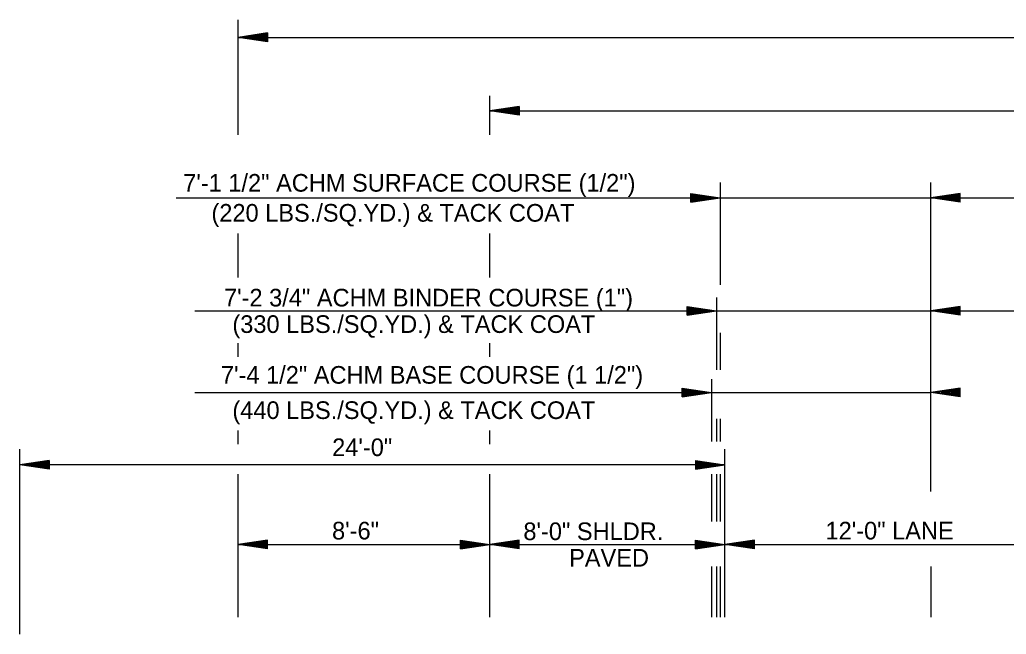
# Model space of a CAD drawing. Extents: x 1371763 to 1372860, y 385599 to 385872.
# Drawn here: x 1372318.58 to 1372352.15, y 385623.49 to 385644.38 of the extents above; entities that cross this region are included whole.
import ezdxf

# ---------------------------------------------------------------- set-up
doc = ezdxf.new("R2010")
doc.units = 0
doc.layers.add('R_Draft', color=7, linetype='Continuous')

msp = doc.modelspace()

# ---------------------------------------------------------------- linework, layer by layer
at = {"layer": 'R_Draft'}
for p, q in [((1372326.012, 385640.475), (1372326.012, 385644.385)), ((1372327.012, 385643.935), (1372326.012, 385643.785)), ((1372326.012, 385643.785), (1372395.148, 385643.785)), ((1372327.012, 385643.635), (1372326.012, 385643.785)), ((1372327.012, 385643.91), (1372326.179, 385643.785)), ((1372327.012, 385643.66), (1372326.179, 385643.785)), ((1372327.012, 385643.884), (1372326.351, 385643.785)), ((1372327.012, 385643.685), (1372326.351, 385643.785)), ((1372327.012, 385643.859), (1372326.517, 385643.785)), ((1372327.012, 385643.71), (1372326.517, 385643.785)), ((1372327.012, 385643.833), (1372326.687, 385643.785)), ((1372327.012, 385643.736), (1372326.687, 385643.785)), ((1372327.012, 385643.808), (1372326.854, 385643.785)), ((1372327.012, 385643.761), (1372326.854, 385643.785)), ((1372327.012, 385643.935), (1372327.012, 385643.635)), ((1372334.576, 385640.475), (1372334.576, 385641.795)), ((1372335.576, 385641.435), (1372334.576, 385641.285)), ((1372335.576, 385641.41), (1372334.743, 385641.285)), ((1372335.576, 385641.384), (1372334.915, 385641.285)), ((1372335.576, 385641.359), (1372335.082, 385641.285)), ((1372335.576, 385641.333), (1372335.251, 385641.285)), ((1372335.576, 385641.435), (1372335.576, 385641.135)), ((1372334.576, 385641.285), (1372386.577, 385641.285)), ((1372335.576, 385641.135), (1372334.576, 385641.285)), ((1372335.576, 385641.16), (1372334.743, 385641.285)), ((1372335.576, 385641.185), (1372334.915, 385641.285)), ((1372335.576, 385641.21), (1372335.082, 385641.285)), ((1372335.576, 385641.236), (1372335.251, 385641.285)), ((1372335.576, 385641.308), (1372335.418, 385641.285)), ((1372335.576, 385641.261), (1372335.418, 385641.285)), ((1372342.411, 385638.855), (1372342.411, 385635.372)), ((1372349.578, 385628.34), (1372349.579, 385638.855)), ((1372323.903, 385638.328), (1372349.579, 385638.329)), ((1372341.411, 385638.479), (1372342.411, 385638.329)), ((1372341.411, 385638.179), (1372341.411, 385638.479)), ((1372341.411, 385638.454), (1372342.244, 385638.329)), ((1372341.411, 385638.428), (1372342.072, 385638.329)), ((1372341.411, 385638.403), (1372341.905, 385638.329)), ((1372341.411, 385638.378), (1372341.736, 385638.329)), ((1372341.411, 385638.352), (1372341.569, 385638.329)), ((1372341.411, 385638.179), (1372342.411, 385638.329)), ((1372341.411, 385638.28), (1372341.736, 385638.329)), ((1372341.411, 385638.229), (1372342.072, 385638.329)), ((1372341.411, 385638.204), (1372342.244, 385638.329)), ((1372341.411, 385638.254), (1372341.905, 385638.329)), ((1372341.411, 385638.305), (1372341.569, 385638.329)), ((1372350.579, 385638.479), (1372349.579, 385638.329)), ((1372349.579, 385638.329), (1372371.579, 385638.329)), ((1372350.579, 385638.179), (1372349.579, 385638.329)), ((1372350.579, 385638.454), (1372349.746, 385638.329)), ((1372350.579, 385638.204), (1372349.746, 385638.329)), ((1372350.579, 385638.428), (1372349.918, 385638.329)), ((1372350.579, 385638.229), (1372349.918, 385638.329)), ((1372350.579, 385638.403), (1372350.085, 385638.329)), ((1372350.579, 385638.254), (1372350.085, 385638.329)), ((1372350.579, 385638.378), (1372350.254, 385638.329)), ((1372350.579, 385638.28), (1372350.254, 385638.329)), ((1372350.579, 385638.352), (1372350.421, 385638.329)), ((1372350.579, 385638.305), (1372350.421, 385638.329)), ((1372350.579, 385638.179), (1372350.579, 385638.479)), ((1372326.011, 385635.621), (1372326.012, 385637.121)), ((1372334.576, 385635.621), (1372334.576, 385637.121)), ((1372341.285, 385634.635), (1372342.285, 385634.485)), ((1372341.285, 385634.335), (1372341.285, 385634.635)), ((1372342.285, 385634.935), (1372342.285, 385632.483)), ((1372350.579, 385634.635), (1372349.579, 385634.485)), ((1372350.579, 385634.335), (1372350.579, 385634.635)), ((1372324.538, 385634.485), (1372349.579, 385634.485)), ((1372341.285, 385634.61), (1372342.118, 385634.485)), ((1372341.285, 385634.584), (1372341.946, 385634.485)), ((1372341.285, 385634.559), (1372341.779, 385634.485)), ((1372341.285, 385634.534), (1372341.61, 385634.485)), ((1372341.285, 385634.508), (1372341.443, 385634.485)), ((1372341.285, 385634.335), (1372342.285, 385634.485)), ((1372341.285, 385634.436), (1372341.61, 385634.485)), ((1372341.285, 385634.385), (1372341.946, 385634.485)), ((1372341.285, 385634.36), (1372342.118, 385634.485)), ((1372341.285, 385634.41), (1372341.779, 385634.485)), ((1372341.285, 385634.461), (1372341.443, 385634.485)), ((1372350.579, 385634.335), (1372349.579, 385634.485)), ((1372349.579, 385634.485), (1372371.579, 385634.485)), ((1372350.579, 385634.61), (1372349.746, 385634.485)), ((1372350.579, 385634.36), (1372349.746, 385634.485)), ((1372350.579, 385634.584), (1372349.918, 385634.485)), ((1372350.579, 385634.385), (1372349.918, 385634.485)), ((1372350.579, 385634.559), (1372350.085, 385634.485)), ((1372350.579, 385634.41), (1372350.085, 385634.485)), ((1372350.579, 385634.534), (1372350.254, 385634.485)), ((1372350.579, 385634.436), (1372350.254, 385634.485)), ((1372350.579, 385634.508), (1372350.421, 385634.485)), ((1372350.579, 385634.461), (1372350.421, 385634.485)), ((1372342.411, 385633.735), (1372342.411, 385632.483)), ((1372326.012, 385632.924), (1372326.012, 385633.389)), ((1372334.576, 385632.924), (1372334.576, 385633.389)), ((1372342.116, 385632.159), (1372342.116, 385630.044)), ((1372324.538, 385631.709), (1372349.579, 385631.709)), ((1372341.116, 385631.859), (1372342.116, 385631.709)), ((1372341.116, 385631.559), (1372341.116, 385631.859)), ((1372341.116, 385631.834), (1372341.949, 385631.709)), ((1372341.116, 385631.809), (1372341.777, 385631.709)), ((1372341.116, 385631.784), (1372341.611, 385631.709)), ((1372341.116, 385631.758), (1372341.441, 385631.709)), ((1372341.116, 385631.733), (1372341.274, 385631.709)), ((1372341.116, 385631.559), (1372342.116, 385631.709)), ((1372341.116, 385631.661), (1372341.441, 385631.709)), ((1372341.116, 385631.61), (1372341.777, 385631.709)), ((1372341.116, 385631.584), (1372341.949, 385631.709)), ((1372341.116, 385631.635), (1372341.611, 385631.709)), ((1372341.116, 385631.686), (1372341.274, 385631.709)), ((1372350.578, 385631.859), (1372349.578, 385631.709)), ((1372350.578, 385631.559), (1372349.578, 385631.709)), ((1372350.578, 385631.834), (1372349.745, 385631.709)), ((1372350.578, 385631.584), (1372349.745, 385631.709)), ((1372350.578, 385631.809), (1372349.917, 385631.709)), ((1372350.578, 385631.61), (1372349.917, 385631.709)), ((1372350.578, 385631.784), (1372350.084, 385631.709)), ((1372350.578, 385631.635), (1372350.084, 385631.709)), ((1372350.578, 385631.758), (1372350.253, 385631.709)), ((1372350.578, 385631.661), (1372350.253, 385631.709)), ((1372350.578, 385631.733), (1372350.42, 385631.709)), ((1372350.578, 385631.686), (1372350.42, 385631.709)), ((1372350.578, 385631.559), (1372350.578, 385631.859)), ((1372342.285, 385630.809), (1372342.285, 385630.044)), ((1372342.411, 385630.809), (1372342.411, 385630.044)), ((1372326.012, 385629.95), (1372326.012, 385630.416)), ((1372334.576, 385629.95), (1372334.576, 385630.416)), ((1372318.576, 385623.489), (1372318.576, 385629.787)), ((1372342.576, 385624.074), (1372342.576, 385629.787)), ((1372319.576, 385629.397), (1372318.576, 385629.247)), ((1372319.576, 385629.097), (1372318.576, 385629.247)), ((1372342.576, 385629.247), (1372318.576, 385629.247)), ((1372319.576, 385629.372), (1372318.743, 385629.247)), ((1372319.576, 385629.122), (1372318.743, 385629.247)), ((1372319.576, 385629.346), (1372318.915, 385629.247)), ((1372319.576, 385629.147), (1372318.915, 385629.247)), ((1372319.576, 385629.321), (1372319.082, 385629.247)), ((1372319.576, 385629.172), (1372319.082, 385629.247)), ((1372319.576, 385629.295), (1372319.251, 385629.247)), ((1372319.576, 385629.198), (1372319.251, 385629.247)), ((1372319.576, 385629.27), (1372319.418, 385629.247)), ((1372319.576, 385629.223), (1372319.418, 385629.247)), ((1372319.576, 385629.397), (1372319.576, 385629.097)), ((1372341.576, 385629.397), (1372342.576, 385629.247)), ((1372341.576, 385629.397), (1372341.576, 385629.097)), ((1372341.576, 385629.372), (1372342.409, 385629.247)), ((1372341.576, 385629.346), (1372342.237, 385629.247)), ((1372341.576, 385629.321), (1372342.071, 385629.247)), ((1372341.576, 385629.295), (1372341.901, 385629.247)), ((1372341.576, 385629.27), (1372341.734, 385629.247)), ((1372341.576, 385629.097), (1372342.576, 385629.247)), ((1372341.576, 385629.198), (1372341.901, 385629.247)), ((1372341.576, 385629.147), (1372342.237, 385629.247)), ((1372341.576, 385629.122), (1372342.409, 385629.247)), ((1372341.576, 385629.172), (1372342.071, 385629.247)), ((1372341.576, 385629.223), (1372341.734, 385629.247)), ((1372326.011, 385624.074), (1372326.012, 385628.938)), ((1372334.576, 385624.074), (1372334.576, 385628.937)), ((1372342.116, 385628.936), (1372342.116, 385627.327)), ((1372342.285, 385628.936), (1372342.285, 385627.327)), ((1372342.411, 385628.936), (1372342.411, 385627.327)), ((1372327.012, 385626.69), (1372326.012, 385626.54)), ((1372327.012, 385626.665), (1372326.179, 385626.54)), ((1372327.012, 385626.64), (1372326.351, 385626.54)), ((1372327.012, 385626.615), (1372326.517, 385626.54)), ((1372327.012, 385626.589), (1372326.687, 385626.54)), ((1372327.012, 385626.564), (1372326.854, 385626.54)), ((1372327.012, 385626.39), (1372327.012, 385626.69)), ((1372333.576, 385626.69), (1372334.576, 385626.54)), ((1372333.576, 385626.39), (1372333.576, 385626.69)), ((1372333.576, 385626.665), (1372334.409, 385626.54)), ((1372333.576, 385626.64), (1372334.237, 385626.54)), ((1372333.576, 385626.615), (1372334.071, 385626.54)), ((1372333.576, 385626.589), (1372333.901, 385626.54)), ((1372333.576, 385626.564), (1372333.734, 385626.54)), ((1372335.576, 385626.69), (1372334.576, 385626.54)), ((1372335.576, 385626.665), (1372334.743, 385626.54)), ((1372335.576, 385626.64), (1372334.915, 385626.54)), ((1372335.576, 385626.615), (1372335.082, 385626.54)), ((1372335.576, 385626.589), (1372335.251, 385626.54)), ((1372335.576, 385626.564), (1372335.418, 385626.54)), ((1372335.576, 385626.39), (1372335.576, 385626.69)), ((1372341.576, 385626.69), (1372342.576, 385626.54)), ((1372341.576, 385626.39), (1372341.576, 385626.69)), ((1372341.576, 385626.665), (1372342.409, 385626.54)), ((1372341.576, 385626.64), (1372342.237, 385626.54)), ((1372341.576, 385626.615), (1372342.071, 385626.54)), ((1372341.576, 385626.589), (1372341.901, 385626.54)), ((1372341.576, 385626.564), (1372341.734, 385626.54)), ((1372343.576, 385626.69), (1372342.576, 385626.54)), ((1372343.576, 385626.665), (1372342.743, 385626.54)), ((1372343.576, 385626.64), (1372342.915, 385626.54)), ((1372343.576, 385626.615), (1372343.082, 385626.54)), ((1372343.576, 385626.589), (1372343.251, 385626.54)), ((1372343.576, 385626.564), (1372343.418, 385626.54)), ((1372343.576, 385626.39), (1372343.576, 385626.69)), ((1372326.012, 385626.54), (1372334.576, 385626.54)), ((1372327.012, 385626.39), (1372326.012, 385626.54)), ((1372327.012, 385626.415), (1372326.179, 385626.54)), ((1372327.012, 385626.441), (1372326.351, 385626.54)), ((1372327.012, 385626.466), (1372326.517, 385626.54)), ((1372327.012, 385626.492), (1372326.687, 385626.54)), ((1372327.012, 385626.517), (1372326.854, 385626.54)), ((1372333.576, 385626.39), (1372334.576, 385626.54)), ((1372333.576, 385626.492), (1372333.901, 385626.54)), ((1372333.576, 385626.441), (1372334.237, 385626.54)), ((1372333.576, 385626.415), (1372334.409, 385626.54)), ((1372333.576, 385626.466), (1372334.071, 385626.54)), ((1372333.576, 385626.517), (1372333.734, 385626.54)), ((1372334.576, 385626.54), (1372342.576, 385626.54)), ((1372335.576, 385626.39), (1372334.576, 385626.54)), ((1372335.576, 385626.415), (1372334.743, 385626.54)), ((1372335.576, 385626.441), (1372334.915, 385626.54)), ((1372335.576, 385626.466), (1372335.082, 385626.54)), ((1372335.576, 385626.492), (1372335.251, 385626.54)), ((1372335.576, 385626.517), (1372335.418, 385626.54)), ((1372341.576, 385626.39), (1372342.576, 385626.54)), ((1372341.576, 385626.492), (1372341.901, 385626.54)), ((1372341.576, 385626.441), (1372342.237, 385626.54)), ((1372341.576, 385626.415), (1372342.409, 385626.54)), ((1372341.576, 385626.466), (1372342.071, 385626.54)), ((1372341.576, 385626.517), (1372341.734, 385626.54)), ((1372342.576, 385626.54), (1372354.576, 385626.54)), ((1372343.576, 385626.39), (1372342.576, 385626.54)), ((1372343.576, 385626.415), (1372342.743, 385626.54)), ((1372343.576, 385626.441), (1372342.915, 385626.54)), ((1372343.576, 385626.466), (1372343.082, 385626.54)), ((1372343.576, 385626.492), (1372343.251, 385626.54)), ((1372343.576, 385626.517), (1372343.418, 385626.54)), ((1372342.116, 385625.79), (1372342.116, 385624.074)), ((1372342.285, 385625.79), (1372342.285, 385624.074)), ((1372342.411, 385625.79), (1372342.411, 385624.074)), ((1372349.578, 385625.79), (1372349.578, 385624.074))]:
    msp.add_line(p, q, dxfattribs=at)

# ---------------------------------------------------------------- texts
for s, p in [('7\'-1 1/2" ACHM SURFACE COURSE (1/2")', (1372324.14, 385638.539)), ('(220 LBS./SQ.YD.) & TACK COAT', (1372325.101, 385637.519)), ('7\'-2 3/4" ACHM BINDER COURSE (1")', (1372325.528, 385634.635)), ('(330 LBS./SQ.YD.) & TACK COAT', (1372325.814, 385633.735)), ('7\'-4 1/2" ACHM BASE COURSE (1 1/2")', (1372325.424, 385632.009)), ('(440 LBS./SQ.YD.) & TACK COAT', (1372325.814, 385630.809)), ('24\'-0"', (1372329.209, 385629.547)), ('8\'-6"', (1372329.205, 385626.712)), ('8\'-0" SHLDR.', (1372335.716, 385626.69)), ('12\'-0" LANE', (1372345.998, 385626.712)), ('PAVED', (1372337.272, 385625.79))]:
    msp.add_text(s, height=0.6, rotation=360, dxfattribs=at).set_placement(p)

doc.saveas('drawing.dxf')
